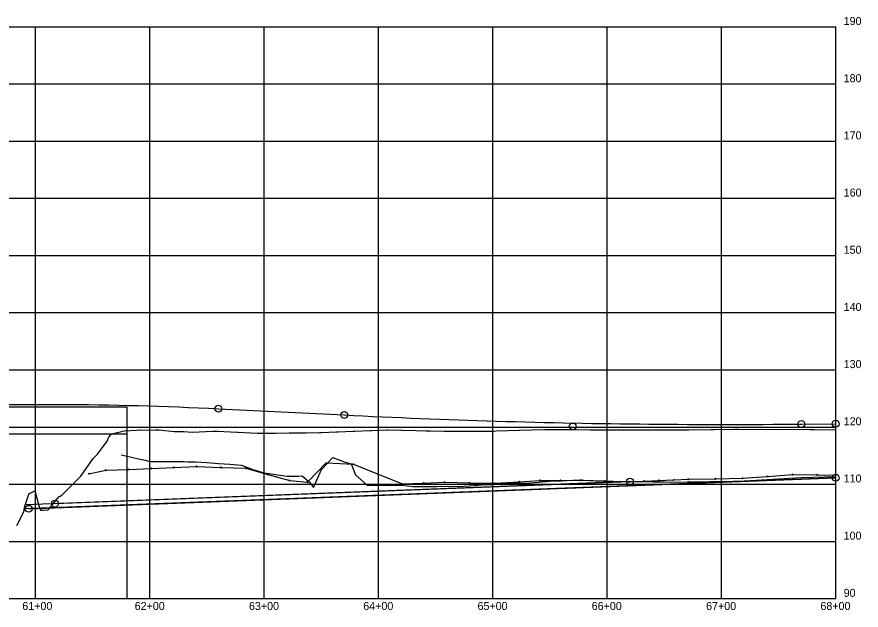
# Model space of a CAD drawing. Extents: x 1191541 to 1200065, y 1475807 to 1480451.
# Drawn here: x 1194690 to 1195429, y 1478932 to 1479451 of the extents above; entities that cross this region are included whole.
import ezdxf

# ---------------------------------------------------------------- set-up
doc = ezdxf.new("R2010")
doc.units = 0
for name, color, linetype in [('Default', 7, 'Continuous'), ('R_Exist Surface', 7, 'Continuous'), ('R_Grid', 7, 'Continuous'), ('R_No Plot', 7, 'Continuous'), ('R_Point Sym', 7, 'Continuous'), ('R_Proposed Const Limits_Fill', 7, 'Continuous'), ('R_Proposed Const Limits_Hand', 7, 'Continuous'), ('R_Vert Alg', 7, 'Continuous'), ('R_Vert Alg Annot', 7, 'Continuous'), ('R_Water', 7, 'Continuous')]:
    doc.layers.add(name, color=color, linetype=linetype)

msp = doc.modelspace()

# ---------------------------------------------------------------- linework, layer by layer
at = {"layer": 'Default'}
msp.add_lwpolyline([(1194753.03, 1479051.69), (1194767.81, 1479054.67), (1194787.62, 1479055.47), (1194807.43, 1479056.26), (1194827.24, 1479057.14), (1194847.05, 1479058.01), (1194868.62, 1479057.26), (1194890.2, 1479056.52), (1194909.43, 1479051.09), (1194928.65, 1479045.67), (1194944.12, 1479044.18), (1194960.6, 1479061.06), (1194984.38, 1479060.11), (1195005.89, 1479051.43), (1195027.41, 1479042.74), (1195045.83, 1479043.53), (1195064.26, 1479044.32), (1195086.09, 1479043.81), (1195107.92, 1479043.31), (1195129.5, 1479044.66), (1195147.54, 1479045.75), (1195165.62, 1479045.88), (1195183.69, 1479046.01), (1195204.63, 1479045.33), (1195225.57, 1479044.65), (1195238.57, 1479045.19), (1195251.56, 1479045.73), (1195264.55, 1479046.27), (1195277.54, 1479046.81), (1195301.21, 1479047.25), (1195324.87, 1479047.7), (1195346.8, 1479049.34), (1195368.74, 1479050.99), (1195390.17, 1479050.69), (1195406.32, 1479050.47)], dxfattribs=at)
at = {"layer": 'R_Exist Surface'}
msp.add_lwpolyline([(1194689.86, 1479006.49), (1194695.97, 1479018.48), (1194696.88, 1479023.2), (1194700.54, 1479034.6), (1194701.04, 1479034.34), (1194705.5, 1479036.66), (1194705.89, 1479035.89), (1194708.91, 1479024.75), (1194710.65, 1479019.79), (1194712.87, 1479019.88), (1194717.31, 1479019.96), (1194726.66, 1479031.34), (1194727.67, 1479031.91), (1194728.55, 1479032.51), (1194729.42, 1479033.35), (1194734.46, 1479038.18), (1194745.9, 1479049.59), (1194756.73, 1479065.08), (1194760.58, 1479068.92), (1194764.95, 1479074.67), (1194768.83, 1479080.14), (1194770.47, 1479083.77), (1194772.2, 1479085.83), (1194772.6, 1479086.26), (1194773.02, 1479086.57), (1194783.75, 1479089.08), (1194794.46, 1479089.81), (1194797.54, 1479089.92), (1194798.19, 1479089.89), (1194811.13, 1479090.19), (1194814.03, 1479090.07), (1194827.5, 1479088.72), (1194835.89, 1479088.71), (1194843.39, 1479088.16), (1194861.51, 1479088.95), (1194864.49, 1479088.92), (1194865.37, 1479088.91), (1194882.45, 1479087.97), (1194883.53, 1479087.96), (1194900.31, 1479087.04), (1194901.58, 1479087.03), (1194902.77, 1479087.04), (1194914.88, 1479087.21), (1194916.16, 1479087.22), (1194928.18, 1479087.39), (1194929.55, 1479087.39), (1194941.49, 1479087.56), (1194942.95, 1479087.57), (1194954.8, 1479087.74), (1194956.41, 1479087.79), (1194969.46, 1479088.3), (1194970.96, 1479088.34), (1194984.14, 1479088.86), (1194985.52, 1479088.9), (1194998.82, 1479089.43), (1195000.09, 1479089.47), (1195013.52, 1479090), (1195014.59, 1479090), (1195026.22, 1479089.76), (1195026.91, 1479089.76), (1195038.87, 1479089.5), (1195039.17, 1479089.5), (1195047.83, 1479089.31), (1195051.35, 1479089.21), (1195051.64, 1479089.2), (1195063.76, 1479088.85), (1195065.04, 1479088.79), (1195085.14, 1479088.89), (1195086.02, 1479088.88), (1195107, 1479088.99), (1195107.07, 1479088.99), (1195109.3, 1479089.06), (1195129.52, 1479089.64), (1195129.82, 1479089.64), (1195151.96, 1479090.26), (1195152.6, 1479090.26), (1195171.61, 1479090.22), (1195173.5, 1479090.21), (1195191.44, 1479090.17), (1195194.47, 1479090.16), (1195213.39, 1479090.09), (1195215.42, 1479090.06), (1195235.36, 1479089.99), (1195236.41, 1479089.97), (1195255.99, 1479090.05), (1195257.14, 1479090.06), (1195276.63, 1479090.13), (1195277.86, 1479090.14), (1195297.28, 1479090.33), (1195299.43, 1479090.33), (1195318.01, 1479090.51), (1195320.98, 1479090.5), (1195338.74, 1479090.49), (1195341.27, 1479090.51), (1195359.37, 1479090.48), (1195361.55, 1479090.5), (1195383.82, 1479090.25), (1195385.73, 1479090.25), (1195387.67, 1479090.25), (1195406.32, 1479090.03)], dxfattribs=at)
at = {"layer": 'R_Grid'}
for p, q in [((1193906.32, 1479442.53), (1195406.32, 1479442.53)), ((1193906.32, 1479442.53), (1195406.32, 1479442.53)), ((1194706.32, 1478942.53), (1194706.32, 1479442.53)), ((1194806.32, 1478942.53), (1194806.32, 1479442.53)), ((1194906.32, 1478942.53), (1194906.32, 1479442.53)), ((1195006.32, 1478942.53), (1195006.32, 1479442.53)), ((1195106.32, 1478942.53), (1195106.32, 1479442.53)), ((1195206.32, 1478942.53), (1195206.32, 1479442.53)), ((1195306.32, 1478942.53), (1195306.32, 1479442.53)), ((1193906.32, 1479392.53), (1195406.32, 1479392.53)), ((1193906.32, 1479342.53), (1195406.32, 1479342.53)), ((1193906.32, 1479292.53), (1195406.32, 1479292.53)), ((1193906.32, 1479242.53), (1195406.32, 1479242.53)), ((1193906.32, 1479192.53), (1195406.32, 1479192.53)), ((1193906.32, 1479142.53), (1195406.32, 1479142.53)), ((1193906.32, 1479092.53), (1195406.32, 1479092.53)), ((1193906.32, 1479042.53), (1195406.32, 1479042.53)), ((1193906.32, 1478992.53), (1195406.32, 1478992.53))]:
    msp.add_line(p, q, dxfattribs=at)
at = {"layer": 'R_No Plot'}
for p, q in [((1194606.32, 1479110.28), (1194786.32, 1479110.28)), ((1194786.32, 1478942.53), (1194786.32, 1479110.28)), ((1194606.32, 1479086.53), (1194786.32, 1479086.53)), ((1195406.32, 1479048.16), (1194696.42, 1479020.84)), ((1195226.32, 1479044.88), (1194697.24, 1479024.52))]:
    msp.add_line(p, q, dxfattribs=at)
at = {"layer": 'R_Point Sym'}
for points in [[(1194767.81, 1479054.67), (1194767.31, 1479055.17), (1194767.81, 1479054.67), (1194767.31, 1479054.17), (1194767.81, 1479054.67), (1194768.31, 1479054.17), (1194767.81, 1479054.67), (1194768.31, 1479055.17)], [(1194787.62, 1479055.47), (1194787.12, 1479055.97), (1194787.62, 1479055.47), (1194787.12, 1479054.97), (1194787.62, 1479055.47), (1194788.12, 1479054.97), (1194787.62, 1479055.47), (1194788.12, 1479055.97)], [(1194807.43, 1479056.26), (1194806.93, 1479056.76), (1194807.43, 1479056.26), (1194806.93, 1479055.76), (1194807.43, 1479056.26), (1194807.93, 1479055.76), (1194807.43, 1479056.26), (1194807.93, 1479056.76)], [(1194827.24, 1479057.14), (1194826.74, 1479057.64), (1194827.24, 1479057.14), (1194826.74, 1479056.64), (1194827.24, 1479057.14), (1194827.74, 1479056.64), (1194827.24, 1479057.14), (1194827.74, 1479057.64)], [(1194847.05, 1479058.01), (1194846.55, 1479058.51), (1194847.05, 1479058.01), (1194846.55, 1479057.51), (1194847.05, 1479058.01), (1194847.55, 1479057.51), (1194847.05, 1479058.01), (1194847.55, 1479058.51)], [(1194868.62, 1479057.26), (1194868.12, 1479057.76), (1194868.62, 1479057.26), (1194868.12, 1479056.76), (1194868.62, 1479057.26), (1194869.12, 1479056.76), (1194868.62, 1479057.26), (1194869.12, 1479057.76)], [(1194890.2, 1479056.52), (1194889.7, 1479057.02), (1194890.2, 1479056.52), (1194889.7, 1479056.02), (1194890.2, 1479056.52), (1194890.7, 1479056.02), (1194890.2, 1479056.52), (1194890.7, 1479057.02)], [(1194960.6, 1479061.06), (1194960.1, 1479061.56), (1194960.6, 1479061.06), (1194960.1, 1479060.56), (1194960.6, 1479061.06), (1194961.1, 1479060.56), (1194960.6, 1479061.06), (1194961.1, 1479061.56)], [(1194984.38, 1479060.11), (1194983.88, 1479060.61), (1194984.38, 1479060.11), (1194983.88, 1479059.61), (1194984.38, 1479060.11), (1194984.88, 1479059.61), (1194984.38, 1479060.11), (1194984.88, 1479060.61)], [(1194753.03, 1479051.69), (1194752.53, 1479052.19), (1194753.03, 1479051.69), (1194752.53, 1479051.19), (1194753.03, 1479051.69), (1194753.53, 1479051.19), (1194753.03, 1479051.69), (1194753.53, 1479052.19)], [(1194909.43, 1479051.09), (1194908.93, 1479051.59), (1194909.43, 1479051.09), (1194908.93, 1479050.59), (1194909.43, 1479051.09), (1194909.93, 1479050.59), (1194909.43, 1479051.09), (1194909.93, 1479051.59)], [(1195005.89, 1479051.43), (1195005.39, 1479051.93), (1195005.89, 1479051.43), (1195005.39, 1479050.93), (1195005.89, 1479051.43), (1195006.39, 1479050.93), (1195005.89, 1479051.43), (1195006.39, 1479051.93)], [(1195277.54, 1479046.81), (1195277.04, 1479047.31), (1195277.54, 1479046.81), (1195277.04, 1479046.31), (1195277.54, 1479046.81), (1195278.04, 1479046.31), (1195277.54, 1479046.81), (1195278.04, 1479047.31)], [(1195301.21, 1479047.25), (1195300.71, 1479047.75), (1195301.21, 1479047.25), (1195300.71, 1479046.75), (1195301.21, 1479047.25), (1195301.71, 1479046.75), (1195301.21, 1479047.25), (1195301.71, 1479047.75)], [(1195324.87, 1479047.7), (1195324.37, 1479048.2), (1195324.87, 1479047.7), (1195324.37, 1479047.2), (1195324.87, 1479047.7), (1195325.37, 1479047.2), (1195324.87, 1479047.7), (1195325.37, 1479048.2)], [(1195346.8, 1479049.34), (1195346.3, 1479049.84), (1195346.8, 1479049.34), (1195346.3, 1479048.84), (1195346.8, 1479049.34), (1195347.3, 1479048.84), (1195346.8, 1479049.34), (1195347.3, 1479049.84)], [(1195368.74, 1479050.99), (1195368.24, 1479051.49), (1195368.74, 1479050.99), (1195368.24, 1479050.49), (1195368.74, 1479050.99), (1195369.24, 1479050.49), (1195368.74, 1479050.99), (1195369.24, 1479051.49)], [(1195390.17, 1479050.69), (1195389.67, 1479051.19), (1195390.17, 1479050.69), (1195389.67, 1479050.19), (1195390.17, 1479050.69), (1195390.67, 1479050.19), (1195390.17, 1479050.69), (1195390.67, 1479051.19)], [(1194928.65, 1479045.67), (1194928.15, 1479046.17), (1194928.65, 1479045.67), (1194928.15, 1479045.17), (1194928.65, 1479045.67), (1194929.15, 1479045.17), (1194928.65, 1479045.67), (1194929.15, 1479046.17)], [(1194944.12, 1479044.18), (1194943.62, 1479044.68), (1194944.12, 1479044.18), (1194943.62, 1479043.68), (1194944.12, 1479044.18), (1194944.62, 1479043.68), (1194944.12, 1479044.18), (1194944.62, 1479044.68)], [(1195027.41, 1479042.74), (1195026.91, 1479043.24), (1195027.41, 1479042.74), (1195026.91, 1479042.24), (1195027.41, 1479042.74), (1195027.91, 1479042.24), (1195027.41, 1479042.74), (1195027.91, 1479043.24)], [(1195045.83, 1479043.53), (1195045.33, 1479044.03), (1195045.83, 1479043.53), (1195045.33, 1479043.03), (1195045.83, 1479043.53), (1195046.33, 1479043.03), (1195045.83, 1479043.53), (1195046.33, 1479044.03)], [(1195064.26, 1479044.32), (1195063.76, 1479044.82), (1195064.26, 1479044.32), (1195063.76, 1479043.82), (1195064.26, 1479044.32), (1195064.76, 1479043.82), (1195064.26, 1479044.32), (1195064.76, 1479044.82)], [(1195086.09, 1479043.81), (1195085.59, 1479044.31), (1195086.09, 1479043.81), (1195085.59, 1479043.31), (1195086.09, 1479043.81), (1195086.59, 1479043.31), (1195086.09, 1479043.81), (1195086.59, 1479044.31)], [(1195107.92, 1479043.31), (1195107.42, 1479043.81), (1195107.92, 1479043.31), (1195107.42, 1479042.81), (1195107.92, 1479043.31), (1195108.42, 1479042.81), (1195107.92, 1479043.31), (1195108.42, 1479043.81)], [(1195129.5, 1479044.66), (1195129, 1479045.16), (1195129.5, 1479044.66), (1195129, 1479044.16), (1195129.5, 1479044.66), (1195130, 1479044.16), (1195129.5, 1479044.66), (1195130, 1479045.16)], [(1195147.54, 1479045.75), (1195147.04, 1479046.25), (1195147.54, 1479045.75), (1195147.04, 1479045.25), (1195147.54, 1479045.75), (1195148.04, 1479045.25), (1195147.54, 1479045.75), (1195148.04, 1479046.25)], [(1195165.62, 1479045.88), (1195165.12, 1479046.38), (1195165.62, 1479045.88), (1195165.12, 1479045.38), (1195165.62, 1479045.88), (1195166.12, 1479045.38), (1195165.62, 1479045.88), (1195166.12, 1479046.38)], [(1195183.69, 1479046.01), (1195183.19, 1479046.51), (1195183.69, 1479046.01), (1195183.19, 1479045.51), (1195183.69, 1479046.01), (1195184.19, 1479045.51), (1195183.69, 1479046.01), (1195184.19, 1479046.51)], [(1195204.63, 1479045.33), (1195204.13, 1479045.83), (1195204.63, 1479045.33), (1195204.13, 1479044.83), (1195204.63, 1479045.33), (1195205.13, 1479044.83), (1195204.63, 1479045.33), (1195205.13, 1479045.83)], [(1195225.57, 1479044.65), (1195225.07, 1479045.15), (1195225.57, 1479044.65), (1195225.07, 1479044.15), (1195225.57, 1479044.65), (1195226.07, 1479044.15), (1195225.57, 1479044.65), (1195226.07, 1479045.15)], [(1195238.57, 1479045.19), (1195238.07, 1479045.69), (1195238.57, 1479045.19), (1195238.07, 1479044.69), (1195238.57, 1479045.19), (1195239.07, 1479044.69), (1195238.57, 1479045.19), (1195239.07, 1479045.69)], [(1195251.56, 1479045.73), (1195251.06, 1479046.23), (1195251.56, 1479045.73), (1195251.06, 1479045.23), (1195251.56, 1479045.73), (1195252.06, 1479045.23), (1195251.56, 1479045.73), (1195252.06, 1479046.23)], [(1195264.55, 1479046.27), (1195264.05, 1479046.77), (1195264.55, 1479046.27), (1195264.05, 1479045.77), (1195264.55, 1479046.27), (1195265.05, 1479045.77), (1195264.55, 1479046.27), (1195265.05, 1479046.77)]]:
    msp.add_lwpolyline(points, dxfattribs=at)
at = {"layer": 'R_Proposed Const Limits_Fill'}
msp.add_lwpolyline([(1194781.32, 1479068.18), (1194786.32, 1479066.91), (1194796.32, 1479064.6), (1194800.64, 1479063.72), (1194806.32, 1479062.49), (1194816.32, 1479062.37), (1194826.32, 1479062.35), (1194836.32, 1479062.25), (1194839.47, 1479062.22), (1194846.32, 1479062.15), (1194856.32, 1479061.45), (1194866.32, 1479060.76), (1194876.32, 1479060.01), (1194886.32, 1479059.21), (1194896.32, 1479055.37), (1194906.32, 1479052.43), (1194916.32, 1479051.02), (1194926.32, 1479049.6), (1194936.32, 1479049.43), (1194939.47, 1479049.72), (1194946.32, 1479044.05), (1194949.47, 1479039.67), (1194956.32, 1479055.31), (1194966.32, 1479065.89), (1194976.32, 1479062.22), (1194982.47, 1479060.24), (1194986.32, 1479050.81), (1194996.32, 1479041.69), (1195006.32, 1479041.68), (1195014.47, 1479041.59), (1195016.32, 1479041.61), (1195024.47, 1479041.66), (1195026.32, 1479041.62), (1195036.32, 1479040.65), (1195046.32, 1479040.6), (1195056.32, 1479040.6), (1195057.47, 1479040.61), (1195066.32, 1479040.69), (1195076.32, 1479040.65), (1195086.32, 1479041.1), (1195096.32, 1479041.93), (1195106.32, 1479042.18), (1195116.32, 1479043.35), (1195126.32, 1479043.8), (1195136.32, 1479043.47), (1195146.32, 1479044.19), (1195156.32, 1479045.08), (1195166.32, 1479045.55), (1195176.32, 1479046.07), (1195186.32, 1479045.94), (1195196.32, 1479045.54), (1195206.32, 1479045.17), (1195216.32, 1479044.73), (1195226.32, 1479044.88), (1195236.32, 1479044.75), (1195246.32, 1479044.63), (1195256.32, 1479044.5), (1195266.32, 1479044.41), (1195276.32, 1479044.5), (1195286.32, 1479044.56), (1195296.32, 1479044.79), (1195306.32, 1479045.01), (1195316.32, 1479045.25), (1195326.32, 1479045.54), (1195336.32, 1479046.14), (1195346.32, 1479046.77), (1195356.32, 1479047.31), (1195366.32, 1479047.93), (1195376.32, 1479048.31), (1195386.32, 1479048.58), (1195396.32, 1479048.93), (1195406.32, 1479049.22)], dxfattribs=at)
at = {"layer": 'R_Vert Alg'}
for p, q in [((1194866.32, 1479108.53), (1194976.32, 1479103.03)), ((1195206.32, 1479095.31), (1195206.32, 1479095.51)), ((1195376.32, 1479095.13), (1195406.32, 1479095.44)), ((1194700.32, 1479020.99), (1195406.32, 1479048.16)), ((1194700.32, 1479020.99), (1195406.32, 1479048.16)), ((1194723.32, 1479025.52), (1195226.32, 1479044.88)), ((1194723.32, 1479025.52), (1195226.32, 1479044.88)), ((1194723.32, 1479025.52), (1195226.32, 1479044.88))]:
    msp.add_line(p, q, dxfattribs=at)
for points in [[(1194682.57, 1479112.19), (1194691.32, 1479112.26), (1194700.07, 1479112.32), (1194708.82, 1479112.34), (1194717.57, 1479112.34), (1194726.32, 1479112.32), (1194735.07, 1479112.27), (1194743.82, 1479112.2), (1194752.57, 1479112.1), (1194761.32, 1479111.97), (1194770.07, 1479111.82), (1194778.82, 1479111.65), (1194787.57, 1479111.45), (1194796.32, 1479111.22), (1194805.07, 1479110.98), (1194813.82, 1479110.7), (1194822.57, 1479110.4), (1194831.32, 1479110.08), (1194840.07, 1479109.73), (1194848.82, 1479109.35), (1194857.57, 1479108.95), (1194866.32, 1479108.53)], [(1194976.32, 1479103.03), (1194984.66, 1479102.62), (1194992.99, 1479102.21), (1195001.32, 1479101.82), (1195009.66, 1479101.44), (1195017.99, 1479101.07), (1195026.32, 1479100.72), (1195034.66, 1479100.37), (1195042.99, 1479100.03), (1195051.32, 1479099.7), (1195059.66, 1479099.39), (1195067.99, 1479099.08), (1195076.32, 1479098.78), (1195084.66, 1479098.5), (1195092.99, 1479098.22), (1195101.32, 1479097.96), (1195109.66, 1479097.7), (1195117.99, 1479097.46), (1195126.32, 1479097.23), (1195134.66, 1479097.01), (1195142.99, 1479096.79), (1195151.32, 1479096.59), (1195159.66, 1479096.4), (1195167.99, 1479096.22), (1195184.66, 1479095.89), (1195192.99, 1479095.74), (1195201.32, 1479095.61), (1195209.66, 1479095.48), (1195217.99, 1479095.36), (1195226.32, 1479095.25), (1195234.66, 1479095.16), (1195242.99, 1479095.07), (1195251.32, 1479095), (1195259.66, 1479094.93), (1195267.99, 1479094.88), (1195276.32, 1479094.83), (1195284.66, 1479094.8), (1195292.99, 1479094.78), (1195301.32, 1479094.76), (1195309.66, 1479094.76), (1195317.99, 1479094.77), (1195326.32, 1479094.79), (1195334.66, 1479094.82), (1195342.99, 1479094.86), (1195351.32, 1479094.91), (1195359.66, 1479094.97), (1195367.99, 1479095.04), (1195376.32, 1479095.13)]]:
    msp.add_lwpolyline(points, dxfattribs=at)
at = {"layer": 'R_Vert Alg Annot'}
for centre in [(1194866.32, 1479108.53), (1194976.32, 1479103.03), (1195176.32, 1479093.03), (1195376.32, 1479095.13), (1195406.32, 1479095.44), (1195226.32, 1479044.88), (1195226.32, 1479044.88), (1195226.32, 1479044.88), (1195406.32, 1479048.16), (1195406.32, 1479048.16), (1194723.32, 1479025.52), (1194723.32, 1479025.52), (1194723.32, 1479025.52), (1194700.32, 1479020.99), (1194700.32, 1479020.99)]:
    msp.add_circle(centre, 3, dxfattribs=at)
at = {"layer": 'R_Water'}
for p, q in [((1195406.32, 1478942.53), (1195406.32, 1479442.53)), ((1193906.32, 1478942.53), (1195406.32, 1478942.53))]:
    msp.add_line(p, q, dxfattribs=at)

# ---------------------------------------------------------------- texts
at = {"layer": 'R_Proposed Const Limits_Hand'}
for s, p in [('190', (1195413.32, 1479444.03)), ('190', (1195413.32, 1479444.03)), ('180', (1195413.32, 1479394.03)), ('170', (1195413.32, 1479344.03)), ('160', (1195413.32, 1479294.03)), ('150', (1195413.32, 1479244.03)), ('140', (1195413.32, 1479194.03)), ('130', (1195413.32, 1479144.03)), ('120', (1195413.32, 1479094.03)), ('110', (1195413.32, 1479044.03)), ('100', (1195413.32, 1478994.03)), ('90', (1195413.32, 1478944.03)), ('61+00', (1194694.68, 1478932.53)), ('62+00', (1194792.98, 1478932.53)), ('63+00', (1194892.98, 1478932.53)), ('64+00', (1194992.98, 1478932.53)), ('65+00', (1195092.98, 1478932.53)), ('66+00', (1195192.84, 1478932.53)), ('67+00', (1195292.98, 1478932.53)), ('68+00', (1195392.98, 1478932.53))]:
    msp.add_text(s, height=7, dxfattribs=at).set_placement(p)

doc.saveas('drawing.dxf')
